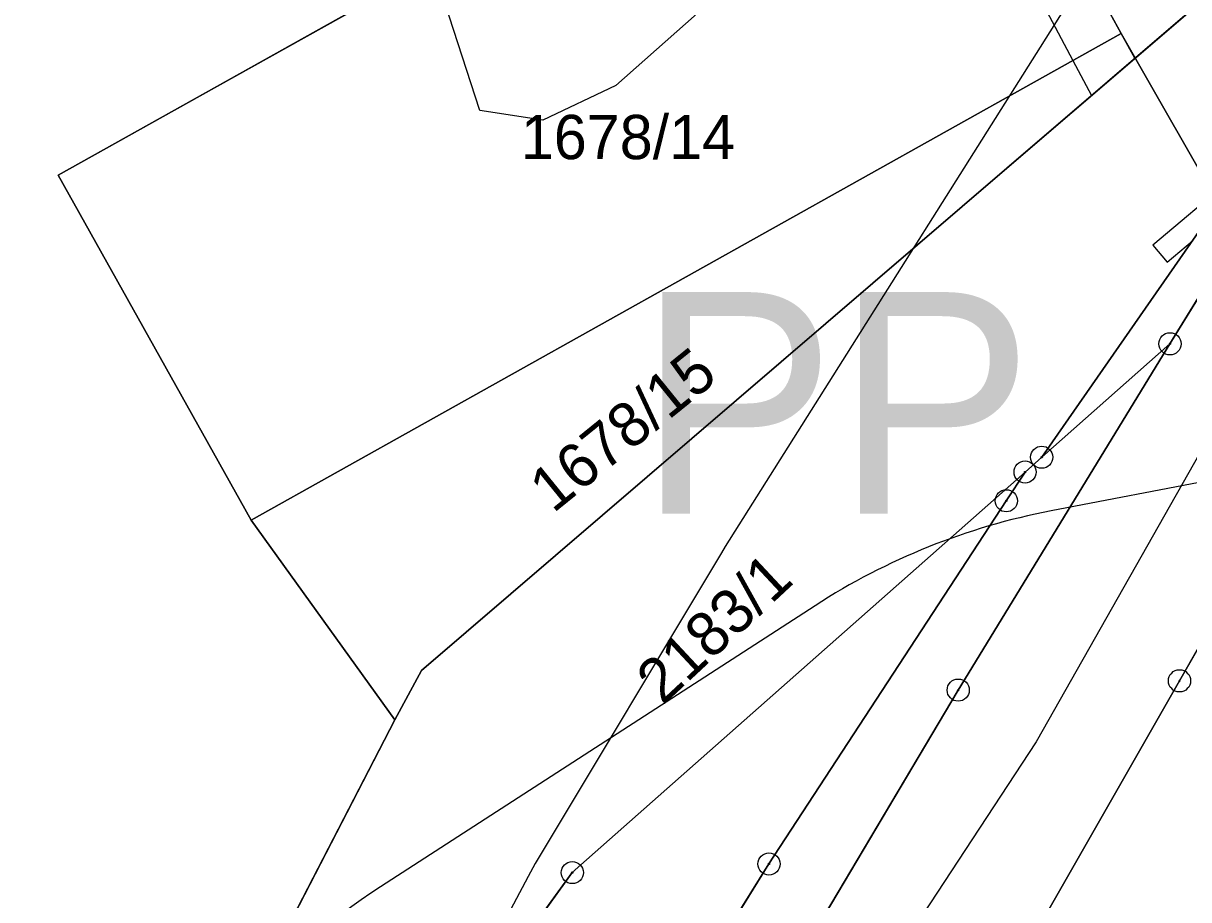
# Model space of a CAD drawing. Extents: x -706130 to -698555, y -971544 to -967260.
# Drawn here: x -704462.3 to -704409.7, y -970459.4 to -970419.8 of the extents above; entities that cross this region are included whole.
import ezdxf

# ---------------------------------------------------------------- set-up
doc = ezdxf.new("R2010")
doc.units = 0
for name, color, linetype in [('BPEJ I-II trida ochrany S', 7, 'Continuous'), ('Docházková izochrona - VLAK N', 7, 'Continuous'), ('Hranice intravilán', 7, 'Continuous'), ('KN_Hranice_parcel', 7, 'Continuous'), ('KN_Parcelni cisla', 7, 'Continuous'), ('KN_Polygon parcely', 7, 'Continuous'), ('KN_POZEMKY_14_OSTATNI PLOCHA', 7, 'Continuous'), ('KN_POZEMKY_7_TTP', 7, 'Continuous'), ('KN_VYUZITI_16_ostatni plocha_silnice', 7, 'Continuous'), ('KN_VYUZITI_17_ostatni plocha_ostatni komunikace', 7, 'Continuous'), ('KN_VYUZITI_23_ostatni plocha_manipulacni plocha', 7, 'Continuous'), ('KN_VYUZITI_26_ostatni plocha_jina plocha', 7, 'Continuous'), ('KN_Věcná břemena k části', 7, 'Continuous'), ('KN_Značky bodu BP', 7, 'Continuous'), ('Komunikace III třídy osy S', 7, 'Continuous'), ('OP lesa 30 m', 7, 'Continuous'), ('OP silnic S', 7, 'Continuous'), ('Plochy doprava silniční - silnice III třídy S', 7, 'Continuous'), ('Plochy smíšené nezastavěného území všeobecné S', 7, 'Continuous'), ('Plochy verejnych prostranstvi - komunikace ostatni S', 7, 'Continuous'), ('Regulační bloky v krajině S', 7, 'Continuous'), ('Regulační bloky zastavěné S', 7, 'Continuous'), ('Regulační kódy zastavěné S', 7, 'Continuous'), ('Trasy cykloturistické N', 7, 'Continuous'), ('VÝŠKOPIS_vrstevnice hlavní', 7, 'Continuous'), ('Zastavene uzemi N', 7, 'Continuous'), ('Zastavene uzemi plochy N', 7, 'Continuous')]:
    doc.layers.add(name, color=color, linetype=linetype)

msp = doc.modelspace()

# ---------------------------------------------------------------- linework, layer by layer
at = {"layer": 'BPEJ I-II trida ochrany S'}
for p, q in [((-704460.72, -970426.66), (-704421.1, -970404.49)), ((-704452.01, -970442.24), (-704460.72, -970426.66)), ((-704399.6, -970431.05), (-704410.11, -970449.5)), ((-704417.08, -970440.07), (-704437.52, -970458.16)), ((-704417.93, -970441.37), (-704417.08, -970440.07)), ((-704428.64, -970457.77), (-704417.93, -970441.37)), ((-704445.53, -970451.26), (-704452.01, -970442.24)), ((-704410.11, -970449.5), (-704424.96, -970475.5)), ((-704456.83, -970473.13), (-704445.53, -970451.26)), ((-704444.57, -970483.37), (-704428.64, -970457.77)), ((-704437.52, -970458.16), (-704455.3, -970482.71))]:
    msp.add_line(p, q, dxfattribs=at)
at = {"layer": 'Docházková izochrona - VLAK N'}
msp.add_circle((-704165.451, -969778.767), 800, dxfattribs=at)
at = {"layer": 'Hranice intravilán'}
msp.add_lwpolyline([(-704386.46, -970409.76), (-704394.69, -970423.1), (-704397.28, -970427.29), (-704398.62, -970429.46), (-704403.083, -970437.165), (-704412.74, -970420.26), (-704413.24, -970419.36)], dxfattribs=at)
at = {"layer": 'KN_Hranice_parcel'}
for p, q in [((-704410.54, -970434.28), (-704416.33, -970439.4)), ((-704416.33, -970439.4), (-704417.08, -970440.07)), ((-704417.93, -970441.37), (-704417.08, -970440.07)), ((-704445.53, -970451.26), (-704452.01, -970442.24)), ((-704456.83, -970473.13), (-704445.53, -970451.26))]:
    msp.add_line(p, q, dxfattribs=at)
for points in [[(-704387.19, -970395.46), (-704392.51, -970404.97), (-704410.54, -970434.28)], [(-704452.01, -970442.24), (-704460.72, -970426.66), (-704421.1, -970404.49)], [(-704416.33, -970439.4), (-704409.13, -970429.05), (-704396.57, -970408.3)], [(-704445.53, -970451.26), (-704444.32, -970449.04), (-704417.91, -970426.34), (-704403.45, -970413.95)], [(-704452.01, -970442.24), (-704412.74, -970420.26), (-704413.24, -970419.36)], [(-704398.62, -970429.46), (-704399.6, -970431.05), (-704410.11, -970449.5), (-704424.96, -970475.5)], [(-704449.76, -970553.12), (-704452.04, -970539.51), (-704449.79, -970513.98), (-704446.53, -970498.08), (-704432.97, -970471.6), (-704420.1, -970449.92), (-704410.54, -970434.28)], [(-704417.08, -970440.07), (-704437.52, -970458.16), (-704455.3, -970482.71), (-704457.12, -970498.24), (-704460.86, -970536.48), (-704460.37, -970544.21)], [(-704457.5, -970545.33), (-704457.1, -970528.92), (-704450.6, -970500.34), (-704444.57, -970483.37), (-704428.64, -970457.77), (-704417.93, -970441.37)]]:
    msp.add_lwpolyline(points, dxfattribs=at)
at = {"layer": 'KN_Polygon parcely'}
for points in [[(-704492.75, -970364), (-704474.11, -970434.34), (-704456.83, -970473.13), (-704445.53, -970451.26), (-704452.01, -970442.24), (-704460.72, -970426.66), (-704421.1, -970404.49)], [(-704392.51, -970404.97), (-704410.54, -970434.28), (-704420.1, -970449.92), (-704432.97, -970471.6), (-704446.53, -970498.08), (-704449.79, -970513.98), (-704452.04, -970539.51), (-704449.76, -970553.12), (-704449.12, -970558.06), (-704448.09, -970560.09), (-704440.4, -970575.2), (-704397.96, -970643.06), (-704390, -970659.17), (-704385.4, -970680.33), (-704389.28, -970704.44), (-704391.73, -970719.71)], [(-704391.73, -970719.71), (-704389.28, -970704.44), (-704388.64, -970691.38), (-704415.64, -970625.27), (-704435.23, -970594.85), (-704456.48, -970566.41), (-704456.72, -970565.07), (-704459.46, -970549.4), (-704460.37, -970544.21), (-704460.86, -970536.48), (-704457.12, -970498.24), (-704455.3, -970482.71), (-704437.52, -970458.16), (-704417.08, -970440.07), (-704416.33, -970439.4), (-704409.13, -970429.05), (-704396.57, -970408.3)], [(-704385.12, -970737.85), (-704377.41, -970702.19), (-704377.6, -970678.33), (-704379.8, -970666.04), (-704384.25, -970653.17), (-704389.48, -970641.61), (-704437.59, -970564.83), (-704444.18, -970537.3), (-704440.81, -970512.35), (-704437.86, -970500.93), (-704429.88, -970483.99), (-704424.96, -970475.5), (-704410.11, -970449.5), (-704399.6, -970431.05), (-704398.62, -970429.46), (-704397.28, -970427.29), (-704394.69, -970423.1), (-704386.46, -970409.76)], [(-704403.45, -970413.95), (-704417.91, -970426.34), (-704444.32, -970449.04), (-704445.53, -970451.26), (-704456.83, -970473.13), (-704462.33, -970484.51), (-704467.66, -970532.1), (-704464.83, -970542.91), (-704459.85, -970569.07), (-704438.13, -970597.66), (-704419.24, -970627.4), (-704392.84, -970693.06), (-704394.53, -970717.38)]]:
    msp.add_lwpolyline(points, dxfattribs=at)
for points in [[(-704396.57, -970408.3), (-704409.13, -970429.05), (-704416.33, -970439.4), (-704410.54, -970434.28), (-704392.51, -970404.97), (-704387.19, -970395.46), (-704388.72, -970394.62), (-704394.66, -970405.16)], [(-704452.01, -970442.24), (-704412.74, -970420.26), (-704413.24, -970419.36), (-704421.1, -970404.49), (-704460.72, -970426.66)], [(-704403.45, -970413.95), (-704413.24, -970419.36), (-704412.74, -970420.26), (-704452.01, -970442.24), (-704445.53, -970451.26), (-704444.32, -970449.04), (-704417.91, -970426.34)], [(-704414.8, -970468.06), (-704390.72, -970463.62), (-704401.99, -970449.95), (-704390.95, -970438.63), (-704389.94, -970437.52), (-704398.62, -970429.46), (-704399.6, -970431.05), (-704410.11, -970449.5), (-704424.96, -970475.5)], [(-704432.97, -970471.6), (-704420.1, -970449.92), (-704410.54, -970434.28), (-704416.33, -970439.4), (-704417.08, -970440.07), (-704417.93, -970441.37), (-704428.64, -970457.77), (-704444.57, -970483.37), (-704450.6, -970500.34), (-704457.1, -970528.92), (-704457.5, -970545.33), (-704457.53, -970546.6), (-704449.76, -970553.12), (-704452.04, -970539.51), (-704449.79, -970513.98), (-704446.53, -970498.08)], [(-704460.37, -970544.21), (-704457.53, -970546.6), (-704457.5, -970545.33), (-704457.1, -970528.92), (-704450.6, -970500.34), (-704444.57, -970483.37), (-704428.64, -970457.77), (-704417.93, -970441.37), (-704417.08, -970440.07), (-704437.52, -970458.16), (-704455.3, -970482.71), (-704457.12, -970498.24), (-704460.86, -970536.48)]]:
    msp.add_lwpolyline(points, close=True, dxfattribs=at)
at = {"layer": 'KN_POZEMKY_14_OSTATNI PLOCHA'}
for p, q in [((-704460.72, -970426.66), (-704421.1, -970404.49)), ((-704410.54, -970434.28), (-704392.51, -970404.97)), ((-704392.51, -970404.97), (-704410.54, -970434.28)), ((-704417.91, -970426.34), (-704403.45, -970413.95)), ((-704403.45, -970413.95), (-704417.91, -970426.34)), ((-704413.24, -970419.36), (-704412.74, -970420.26)), ((-704412.74, -970420.26), (-704413.24, -970419.36)), ((-704412.74, -970420.26), (-704452.01, -970442.24)), ((-704452.01, -970442.24), (-704412.74, -970420.26)), ((-704444.32, -970449.04), (-704417.91, -970426.34)), ((-704417.91, -970426.34), (-704444.32, -970449.04)), ((-704452.01, -970442.24), (-704460.72, -970426.66)), ((-704416.33, -970439.4), (-704409.13, -970429.05)), ((-704409.13, -970429.05), (-704416.33, -970439.4)), ((-704399.6, -970431.05), (-704410.11, -970449.5)), ((-704420.1, -970449.92), (-704410.54, -970434.28)), ((-704410.54, -970434.28), (-704420.1, -970449.92)), ((-704410.54, -970434.28), (-704416.33, -970439.4)), ((-704416.33, -970439.4), (-704410.54, -970434.28)), ((-704416.33, -970439.4), (-704417.08, -970440.07)), ((-704417.08, -970440.07), (-704416.33, -970439.4)), ((-704417.08, -970440.07), (-704437.52, -970458.16)), ((-704417.93, -970441.37), (-704417.08, -970440.07)), ((-704428.64, -970457.77), (-704417.93, -970441.37)), ((-704445.53, -970451.26), (-704452.01, -970442.24)), ((-704445.53, -970451.26), (-704444.32, -970449.04)), ((-704444.32, -970449.04), (-704445.53, -970451.26)), ((-704410.11, -970449.5), (-704424.96, -970475.5)), ((-704432.97, -970471.6), (-704420.1, -970449.92)), ((-704420.1, -970449.92), (-704432.97, -970471.6)), ((-704456.83, -970473.13), (-704445.53, -970451.26)), ((-704444.57, -970483.37), (-704428.64, -970457.77)), ((-704437.52, -970458.16), (-704455.3, -970482.71))]:
    msp.add_line(p, q, dxfattribs=at)
at = {"layer": 'KN_POZEMKY_7_TTP'}
for p, q in [((-704421.1, -970404.49), (-704460.72, -970426.66)), ((-704460.72, -970426.66), (-704452.01, -970442.24)), ((-704410.11, -970449.5), (-704399.6, -970431.05)), ((-704437.52, -970458.16), (-704417.08, -970440.07)), ((-704417.08, -970440.07), (-704417.93, -970441.37)), ((-704417.93, -970441.37), (-704428.64, -970457.77)), ((-704452.01, -970442.24), (-704445.53, -970451.26)), ((-704424.96, -970475.5), (-704410.11, -970449.5)), ((-704445.53, -970451.26), (-704456.83, -970473.13)), ((-704428.64, -970457.77), (-704444.57, -970483.37)), ((-704455.3, -970482.71), (-704437.52, -970458.16))]:
    msp.add_line(p, q, dxfattribs=at)
at = {"layer": 'KN_VYUZITI_16_ostatni plocha_silnice'}
for p, q in [((-704410.54, -970434.28), (-704392.51, -970404.97)), ((-704399.6, -970431.05), (-704410.11, -970449.5)), ((-704420.1, -970449.92), (-704410.54, -970434.28)), ((-704410.11, -970449.5), (-704424.96, -970475.5)), ((-704432.97, -970471.6), (-704420.1, -970449.92))]:
    msp.add_line(p, q, dxfattribs=at)
at = {"layer": 'KN_VYUZITI_17_ostatni plocha_ostatni komunikace'}
for p, q in [((-704417.91, -970426.34), (-704403.45, -970413.95)), ((-704444.32, -970449.04), (-704417.91, -970426.34)), ((-704409.13, -970429.05), (-704416.33, -970439.4)), ((-704416.33, -970439.4), (-704417.08, -970440.07)), ((-704417.08, -970440.07), (-704437.52, -970458.16)), ((-704445.53, -970451.26), (-704444.32, -970449.04)), ((-704456.83, -970473.13), (-704445.53, -970451.26)), ((-704437.52, -970458.16), (-704455.3, -970482.71))]:
    msp.add_line(p, q, dxfattribs=at)
at = {"layer": 'KN_VYUZITI_23_ostatni plocha_manipulacni plocha'}
for p, q in [((-704460.72, -970426.66), (-704421.1, -970404.49)), ((-704403.45, -970413.95), (-704417.91, -970426.34)), ((-704413.24, -970419.36), (-704412.74, -970420.26)), ((-704412.74, -970420.26), (-704413.24, -970419.36)), ((-704412.74, -970420.26), (-704452.01, -970442.24)), ((-704452.01, -970442.24), (-704412.74, -970420.26)), ((-704417.91, -970426.34), (-704444.32, -970449.04)), ((-704452.01, -970442.24), (-704460.72, -970426.66)), ((-704445.53, -970451.26), (-704452.01, -970442.24)), ((-704444.32, -970449.04), (-704445.53, -970451.26))]:
    msp.add_line(p, q, dxfattribs=at)
at = {"layer": 'KN_VYUZITI_26_ostatni plocha_jina plocha'}
for p, q in [((-704392.51, -970404.97), (-704410.54, -970434.28)), ((-704416.33, -970439.4), (-704409.13, -970429.05)), ((-704410.54, -970434.28), (-704420.1, -970449.92)), ((-704410.54, -970434.28), (-704416.33, -970439.4)), ((-704416.33, -970439.4), (-704410.54, -970434.28)), ((-704417.08, -970440.07), (-704416.33, -970439.4)), ((-704417.93, -970441.37), (-704417.08, -970440.07)), ((-704428.64, -970457.77), (-704417.93, -970441.37)), ((-704420.1, -970449.92), (-704432.97, -970471.6)), ((-704444.57, -970483.37), (-704428.64, -970457.77))]:
    msp.add_line(p, q, dxfattribs=at)
at = {"layer": 'KN_Věcná břemena k části'}
for points in [[(-704423.28, -970405.71), (-704414.92, -970421.48), (-704414.08, -970423.06), (-704412.12, -970421.38), (-704412.74, -970420.26), (-704413.24, -970419.36), (-704421.1, -970404.49)], [(-704410.67, -970430.59), (-704409.53, -970429.63), (-704409.13, -970429.05), (-704407.81, -970426.87), (-704411.31, -970429.83)]]:
    msp.add_lwpolyline(points, close=True, dxfattribs=at)
at = {"layer": 'KN_Značky bodu BP'}
for centre, radius in [((-704410.54, -970434.28), 0.5), ((-704410.54, -970434.28), 0.0303), ((-704416.33, -970439.4), 0.5), ((-704417.08, -970440.07), 0.5), ((-704416.33, -970439.4), 0.0303), ((-704417.08, -970440.07), 0.0303), ((-704417.93, -970441.37), 0.5), ((-704417.93, -970441.37), 0.0303), ((-704410.11, -970449.5), 0.5), ((-704420.1, -970449.92), 0.5), ((-704410.11, -970449.5), 0.0303), ((-704420.1, -970449.92), 0.0303), ((-704428.64, -970457.77), 0.5), ((-704437.52, -970458.16), 0.5), ((-704428.64, -970457.77), 0.0303), ((-704437.52, -970458.16), 0.0303)]:
    msp.add_circle(centre, radius, dxfattribs=at)
at = {"layer": 'Komunikace III třídy osy S'}
msp.add_lwpolyline([(-704392.36, -970410.73), (-704399.98, -970422.96), (-704416.579, -970452.251), (-704423.936, -970463.473), (-704430.079, -970474.624), (-704437.32, -970487.74), (-704440.99, -970496.95), (-704443.639, -970506.619), (-704445.45, -970514.71), (-704446.24, -970521.03), (-704446.95, -970529.22), (-704447.27, -970537.94), (-704447.22, -970543.68), (-704446.69, -970550.7), (-704445.73, -970555.16), (-704444.85, -970557.5), (-704443.66, -970559.94), (-704441.03, -970564.8), (-704437.56, -970570.95), (-704394.186, -970641.224)], dxfattribs=at)
at = {"layer": 'OP lesa 30 m'}
for p, q in [((-704392.018, -970437.247), (-704415.908, -970441.827)), ((-704426.562, -970446.106), (-704446.182, -970458.806))]:
    msp.add_line(p, q, dxfattribs=at)
for centre, start, end in [((-704410.26, -970471.29), 100.8526, 122.9149), ((-704429.88, -970483.99), 122.9149, 154.7761)]:
    msp.add_arc(centre, 30, start, end, dxfattribs=at)
at = {"layer": 'OP silnic S'}
msp.add_lwpolyline([(-704412.691, -970414.996), (-704430.611, -970443.433), (-704430.79, -970443.725), (-704439.19, -970457.757), (-704439.514, -970458.336), (-704444.824, -970468.356), (-704445.17, -970469.053), (-704450.92, -970481.413), (-704451.254, -970482.187), (-704454.924, -970491.397), (-704455.085, -970491.82), (-704455.457, -970492.987), (-704458.106, -970502.656)], dxfattribs=at)
at = {"layer": 'Plochy doprava silniční - silnice III třídy S'}
for p, q in [((-704392.51, -970404.97), (-704410.54, -970434.28)), ((-704410.11, -970449.5), (-704399.6, -970431.05)), ((-704410.54, -970434.28), (-704420.1, -970449.92)), ((-704424.96, -970475.5), (-704410.11, -970449.5)), ((-704420.1, -970449.92), (-704432.97, -970471.6))]:
    msp.add_line(p, q, dxfattribs=at)
at = {"layer": 'Plochy smíšené nezastavěného území všeobecné S'}
for p, q in [((-704417.91, -970426.34), (-704403.45, -970413.95)), ((-704399.6, -970431.05), (-704410.11, -970449.5)), ((-704420.1, -970449.92), (-704410.54, -970434.28)), ((-704410.54, -970434.28), (-704416.33, -970439.4)), ((-704416.33, -970439.4), (-704417.08, -970440.07)), ((-704410.11, -970449.5), (-704424.96, -970475.5)), ((-704432.97, -970471.6), (-704420.1, -970449.92)), ((-704456.83, -970473.13), (-704445.53, -970451.26))]:
    msp.add_line(p, q, dxfattribs=at)
for points in [[(-704445.53, -970451.26), (-704444.32, -970449.04), (-704417.91, -970426.34)], [(-704417.08, -970440.07), (-704437.52, -970458.16), (-704455.3, -970482.71)]]:
    msp.add_lwpolyline(points, dxfattribs=at)
at = {"layer": 'Plochy verejnych prostranstvi - komunikace ostatni S'}
for p, q in [((-704410.54, -970434.28), (-704392.51, -970404.97)), ((-704416.33, -970439.4), (-704410.54, -970434.28)), ((-704417.08, -970440.07), (-704416.33, -970439.4)), ((-704445.53, -970451.26), (-704456.83, -970473.13))]:
    msp.add_line(p, q, dxfattribs=at)
for points in [[(-704403.45, -970413.95), (-704417.91, -970426.34), (-704444.32, -970449.04), (-704445.53, -970451.26)], [(-704460.37, -970544.21), (-704460.86, -970536.48), (-704457.12, -970498.24), (-704455.3, -970482.71), (-704437.52, -970458.16), (-704417.08, -970440.07)]]:
    msp.add_lwpolyline(points, dxfattribs=at)
at = {"layer": 'Regulační bloky v krajině S'}
for p, q in [((-704417.91, -970426.34), (-704403.45, -970413.95)), ((-704399.6, -970431.05), (-704410.11, -970449.5)), ((-704420.1, -970449.92), (-704410.54, -970434.28)), ((-704410.54, -970434.28), (-704416.33, -970439.4)), ((-704416.33, -970439.4), (-704417.08, -970440.07)), ((-704410.11, -970449.5), (-704424.96, -970475.5)), ((-704432.97, -970471.6), (-704420.1, -970449.92)), ((-704456.83, -970473.13), (-704445.53, -970451.26))]:
    msp.add_line(p, q, dxfattribs=at)
for points in [[(-704445.53, -970451.26), (-704444.32, -970449.04), (-704417.91, -970426.34)], [(-704417.08, -970440.07), (-704437.52, -970458.16), (-704455.3, -970482.71)]]:
    msp.add_lwpolyline(points, dxfattribs=at)
at = {"layer": 'Regulační bloky zastavěné S'}
for p, q in [((-704392.51, -970404.97), (-704410.54, -970434.28)), ((-704410.54, -970434.28), (-704392.51, -970404.97)), ((-704410.11, -970449.5), (-704399.6, -970431.05)), ((-704410.54, -970434.28), (-704420.1, -970449.92)), ((-704416.33, -970439.4), (-704410.54, -970434.28)), ((-704417.08, -970440.07), (-704416.33, -970439.4)), ((-704424.96, -970475.5), (-704410.11, -970449.5)), ((-704420.1, -970449.92), (-704432.97, -970471.6)), ((-704445.53, -970451.26), (-704456.83, -970473.13))]:
    msp.add_line(p, q, dxfattribs=at)
for points in [[(-704403.45, -970413.95), (-704417.91, -970426.34), (-704444.32, -970449.04), (-704445.53, -970451.26)], [(-704460.37, -970544.21), (-704460.86, -970536.48), (-704457.12, -970498.24), (-704455.3, -970482.71), (-704437.52, -970458.16), (-704417.08, -970440.07)]]:
    msp.add_lwpolyline(points, dxfattribs=at)
at = {"layer": 'Trasy cykloturistické N'}
msp.add_lwpolyline([(-704385.12, -970737.85), (-704377.41, -970702.19), (-704377.6, -970678.33), (-704379.8, -970666.04), (-704389.48, -970641.61), (-704437.59, -970564.83), (-704444.18, -970537.3), (-704440.81, -970512.35), (-704437.86, -970500.93), (-704429.88, -970483.99), (-704424.96, -970475.5), (-704410.11, -970449.5), (-704410.11, -970449.5), (-704398.62, -970429.46), (-704397.28, -970427.29), (-704386.46, -970409.76)], dxfattribs=at)
at = {"layer": 'VÝŠKOPIS_vrstevnice hlavní'}
msp.add_lwpolyline([(-704430.568, -970418.185), (-704435.561, -970422.608), (-704438.843, -970424.177), (-704441.696, -970423.749), (-704451.144, -970394.65)], dxfattribs=at)
at = {"layer": 'Zastavene uzemi N'}
msp.add_lwpolyline([(-704413.24, -970419.36), (-704412.74, -970420.26), (-704403.083, -970437.165), (-704399.6, -970431.05), (-704398.62, -970429.46), (-704389.94, -970437.52), (-704390.95, -970438.63), (-704401.99, -970449.95), (-704390.72, -970463.62), (-704388.89, -970465.85), (-704387.29, -970465.73), (-704386.37, -970466.71), (-704382.69, -970470.66), (-704380.05, -970468.36)], dxfattribs=at)
at = {"layer": 'Zastavene uzemi plochy N'}
msp.add_lwpolyline([(-704413.24, -970419.36), (-704412.74, -970420.26), (-704403.083, -970437.165), (-704399.6, -970431.05), (-704398.62, -970429.46), (-704389.94, -970437.52), (-704390.95, -970438.63), (-704401.99, -970449.95), (-704390.72, -970463.62), (-704388.89, -970465.85), (-704387.29, -970465.73), (-704386.37, -970466.71), (-704382.69, -970470.66), (-704380.05, -970468.36)], dxfattribs=at)

# ---------------------------------------------------------------- texts
at = {"layer": 'KN_Parcelni cisla'}
msp.add_text('1678/14', height=2, dxfattribs=at).set_placement((-704439.84, -970425.94))
for s, rotation, p in [('1678/15', 39, (-704438.385, -970441.96)), ('2183/1', 43, (-704433.44, -970450.631))]:
    msp.add_text(s, height=2, rotation=rotation, dxfattribs=at).set_placement(p)
at = {"layer": 'Regulační kódy zastavěné S'}
msp.add_text('PP', height=10, dxfattribs=at).set_placement((-704434.552, -970441.945))

doc.saveas('drawing.dxf')
